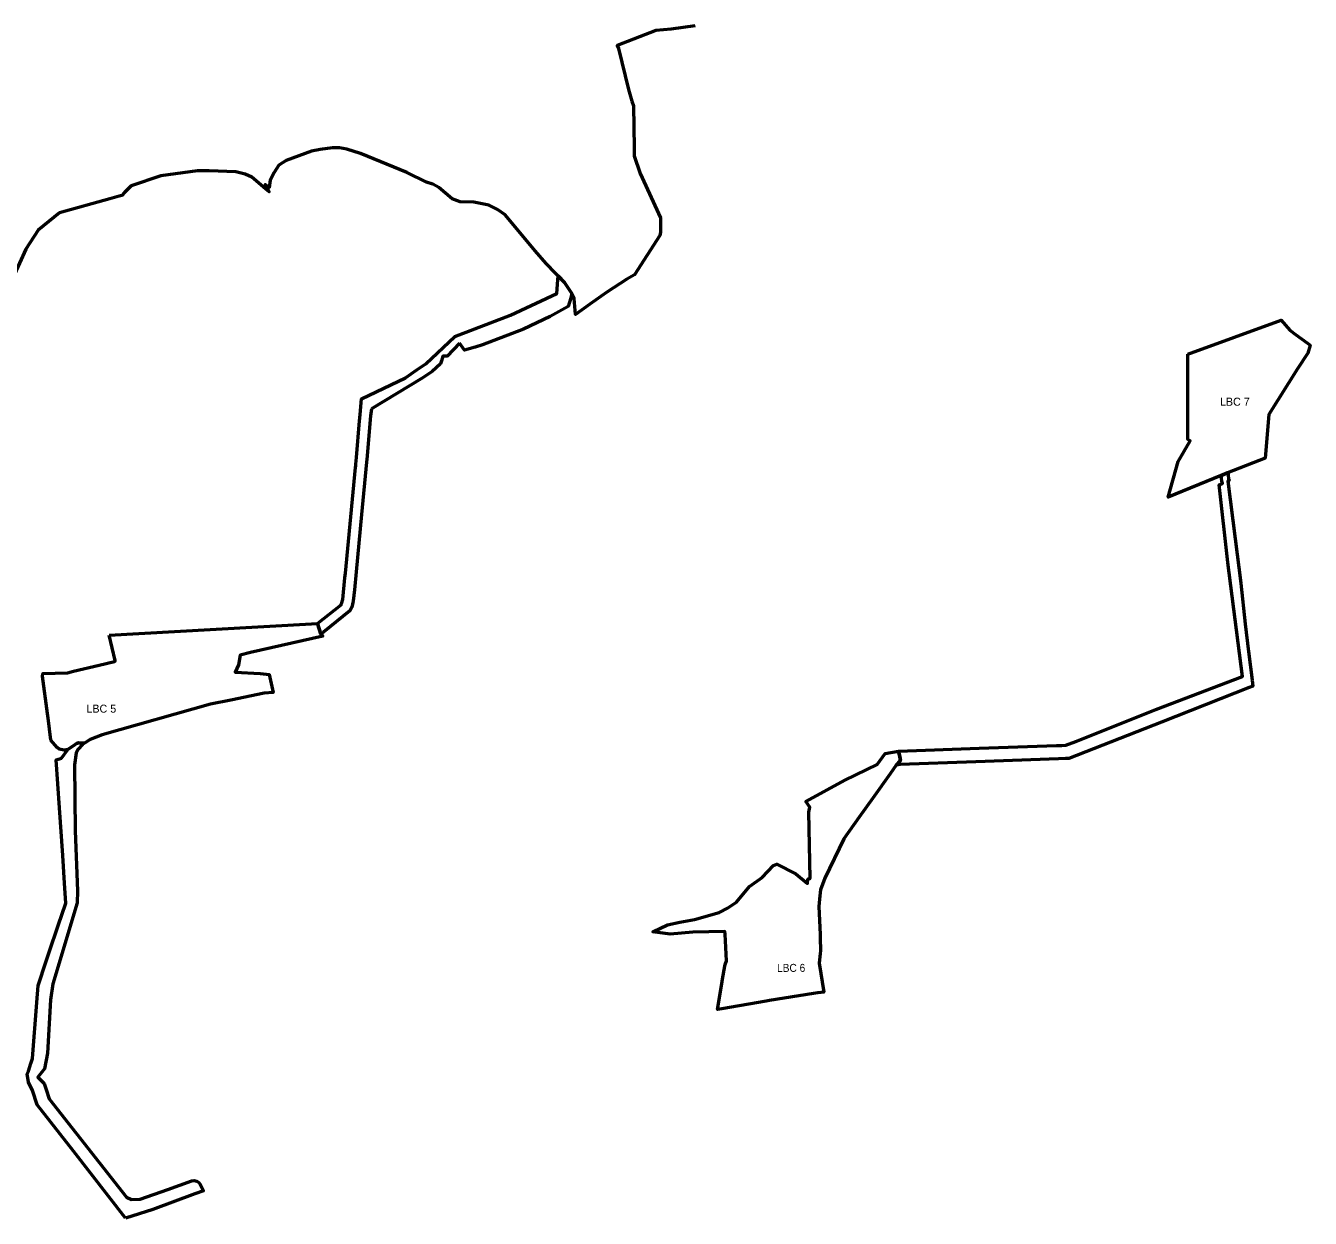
# Model space of a CAD drawing. Extents: x -650276 to -642570, y -1074314 to -1066553.
# Drawn here: x -644496 to -642570, y -1070907 to -1069118 of the extents above; entities that cross this region are included whole.
import ezdxf
from ezdxf.enums import TextEntityAlignment as Align

# ---------------------------------------------------------------- set-up
doc = ezdxf.new("R2010")
doc.units = 0
doc.header["$LTSCALE"] = 4.8
for name, color, linetype, lineweight in [('15', 7, 'Continuous', 53), ('23', 7, 'Continuous', 53), ('27', 7, 'Continuous', 53)]:
    doc.layers.add(name, color=color, linetype=linetype, lineweight=lineweight)
doc.layers.add('63', color=7, linetype='Continuous')

msp = doc.modelspace()

# ---------------------------------------------------------------- linework, layer by layer
at = {"layer": '15'}
for points in [[(-643492.12, -1069118.07), (-643528.05, -1069123.38), (-643550.79, -1069125.24), (-643609.08, -1069147.64), (-643607.02, -1069152.34), (-643592.11, -1069213.99), (-643586.8, -1069231.36), (-643584.68, -1069238.34), (-643583.55, -1069301.43), (-643583.34, -1069313.43), (-643574.54, -1069339.56), (-643543.95, -1069406.4), (-643544.06, -1069427.6), (-643545.07, -1069432.89), (-643582.77, -1069491.76), (-643594.49, -1069498.17), (-643624.65, -1069517.85), (-643649.94, -1069535.93), (-643671.53, -1069551.1), (-643673.34, -1069527.08), (-643676.9, -1069519.91), (-643688.19, -1069503.11), (-643715.22, -1069474.81), (-643731.98, -1069455.66), (-643776.78, -1069401.87), (-643788.63, -1069393.7), (-643801.36, -1069387.23), (-643823.72, -1069382.61), (-643844.28, -1069382.26), (-643856.58, -1069377.59), (-643876.34, -1069360.61), (-643885.22, -1069355.58), (-643894.84, -1069352.76), (-643924.42, -1069338.29), (-643993.91, -1069309.57), (-644014.19, -1069303.36), (-644025.24, -1069301.38), (-644035.89, -1069301.02), (-644054.35, -1069303.55), (-644067.08, -1069306.15), (-644105.5, -1069320.03), (-644116.33, -1069327.36), (-644123.21, -1069338.41), (-644129.09, -1069349.83), (-644130.85, -1069360.64), (-644136.88, -1069356.05), (-644130.55, -1069367.24), (-644136.29, -1069362.5), (-644157.02, -1069345.38), (-644166.58, -1069340.7), (-644180.96, -1069337.42), (-644220.78, -1069335.57), (-644238.42, -1069335.55), (-644293.29, -1069343.17), (-644337.6, -1069358.4), (-644347.56, -1069368.35), (-644351.83, -1069372.62), (-644355.7, -1069373.76)], [(-644355.7, -1069373.76), (-644369.87, -1069377.57), (-644445.36, -1069398.48), (-644477.24, -1069424.8), (-644495.46, -1069453.11), (-644514.85, -1069495)]]:
    msp.add_lwpolyline(points, dxfattribs=at)
at = {"layer": '23'}
for points in [[(-642753.18, -1069610.65), (-642613.34, -1069559.68), (-642600.39, -1069574.87), (-642592.12, -1069580.95), (-642574.11, -1069594.18), (-642569.7, -1069597.42), (-642573.53, -1069609.34), (-642588.93, -1069632.86), (-642631.9, -1069701.07), (-642637.44, -1069766.81), (-642693.99, -1069788.85), (-642703.57, -1069792.88), (-642782.69, -1069824.93), (-642767.89, -1069771.42), (-642750.08, -1069740.57), (-642753.25, -1069738.59)], [(-644370.87, -1070032.13), (-644219.33, -1070023.53), (-644058.55, -1070014.4), (-644053.18, -1070030.57), (-644050.12, -1070033.64), (-644159.02, -1070057.84), (-644174.12, -1070062.16), (-644177.01, -1070076.69), (-644181.81, -1070087.51), (-644144.13, -1070089.47), (-644130.91, -1070091.1), (-644125, -1070117.83), (-644138.24, -1070119.29), (-644188.44, -1070129.43), (-644218.65, -1070135.75), (-644381.21, -1070181.71), (-644399.15, -1070188.55), (-644407.55, -1070194.16), (-644416.67, -1070193.7), (-644419.51, -1070194.76), (-644421.88, -1070196.28), (-644432.53, -1070203.32), (-644438, -1070204.57), (-644445.9, -1070202.83), (-644448.76, -1070200.77), (-644458.1, -1070189.736), (-644462.35, -1070156.65), (-644463.28, -1070149.42), (-644470.55, -1070093.61), (-644470.17, -1070089.43), (-644433.19, -1070088.37), (-644423.99, -1070086.17), (-644385.73, -1070076.96), (-644362.55, -1070071.52), (-644361.571, -1070071.284), (-644361.74, -1070070.32)], [(-643306.64, -1070438.91), (-643304.73, -1070480.95), (-643304.63, -1070486.64), (-643304.23, -1070505.07), (-643304.71, -1070510.01), (-643306.03, -1070524.13), (-643299.3, -1070567.28), (-643307.99, -1070568.66), (-643314.51, -1070569.69), (-643380.35, -1070580.14), (-643385.72, -1070580.86), (-643452.22, -1070592.35), (-643458.42, -1070593.43), (-643452.14, -1070554.77), (-643450.98, -1070547.74), (-643447.79, -1070528.63), (-643446.89, -1070526.01), (-643445.1, -1070520.47), (-643447.14, -1070480.35), (-643447.34, -1070476.49), (-643495.67, -1070477.55), (-643529.45, -1070480.45), (-643555.57, -1070477.1), (-643533.33, -1070466.42), (-643514.92, -1070462.62), (-643492.91, -1070458.54), (-643456.25, -1070448), (-643443.57, -1070441.55), (-643429.94, -1070432.58), (-643410.62, -1070409.09), (-643391.45, -1070395.38), (-643374.72, -1070377.63), (-643369.66, -1070375.29), (-643341.3, -1070390.01), (-643323.48, -1070404.29), (-643323.32, -1070398.24), (-643319.68, -1070396.52), (-643321.63, -1070297.65), (-643320, -1070290.2), (-643326.26, -1070281.43), (-643267.55, -1070249.49), (-643219.4, -1070225.8), (-643207.1, -1070209.72), (-643187.06, -1070205.98), (-643185.16, -1070214.62), (-643184.22, -1070220.08), (-643190.42, -1070226.99), (-643199.67, -1070240.13), (-643225.66, -1070276.41), (-643246.36, -1070305.06), (-643269.16, -1070337.59), (-643297.63, -1070396.36), (-643303.88, -1070414.2), (-643305.45, -1070427.92)]]:
    msp.add_lwpolyline(points, close=True, dxfattribs=at)
at = {"layer": '27'}
for points in [[(-643852.51, -1069584.08), (-643769.08, -1069551.96), (-643699.23, -1069519.48), (-643697.85, -1069499.21), (-643697.686, -1069493.168), (-643688.19, -1069503.11), (-643676.9, -1069519.91), (-643678.24, -1069526.44), (-643682.27, -1069539.41), (-643709.33, -1069554.14), (-643749.64, -1069573.35), (-643811.16, -1069596.45), (-643822.06, -1069600.07), (-643837.72, -1069604.62), (-643845.304, -1069594.087)], [(-643994.36, -1069701.05), (-643992.34, -1069677.76), (-643926.229, -1069646.367), (-643909.616, -1069634.267), (-643895.951, -1069625.069), (-643852.51, -1069584.08)], [(-643845.304, -1069594.087), (-643863.92, -1069613.9), (-643870.44, -1069613.56), (-643872.55, -1069620.75), (-643873.82, -1069625.05), (-643886.62, -1069636.87), (-643901.55, -1069646.92), (-643977.582, -1069692.76)], [(-643977.582, -1069692.76), (-643978.85, -1069703.4), (-643984.44, -1069768.58), (-643984.845, -1069772.863), (-643992.27, -1069851.31), (-644000.52, -1069937.19), (-644003.06, -1069964.06), (-644005.06, -1069981.28), (-644006.96, -1069990.34), (-644009.95, -1069995.74), (-644049.311, -1070027.453), (-644051.913, -1070029.549), (-644053.18, -1070030.57), (-644058.55, -1070014.4), (-644022.99, -1069986.58), (-644022.43, -1069984.87), (-644020.26, -1069978.38), (-644017.15, -1069945.93), (-644016.47, -1069938.99), (-644001.29, -1069780.7), (-644001.04, -1069778.063), (-644000.79, -1069775.42), (-643999.94, -1069765.62), (-643995.17, -1069710.42), (-643994.36, -1069701.05)], [(-644485.61, -1070714.95), (-644491.42, -1070702.64), (-644493.5, -1070689.75), (-644491.82, -1070685.92), (-644488.01, -1070674.2), (-644485.64, -1070666.7), (-644479.06, -1070583.13), (-644476.94, -1070557.45), (-644464.98, -1070521.13), (-644460.5, -1070507.68), (-644447.14, -1070467.28), (-644435.51, -1070433.85), (-644437.53, -1070404.1), (-644440.36, -1070362.62), (-644445.28, -1070290.84), (-644450.15, -1070219.06), (-644442.2, -1070216.72), (-644432.53, -1070203.32), (-644421.88, -1070196.28), (-644419.51, -1070194.76), (-644416.67, -1070193.7), (-644407.55, -1070194.16), (-644410.56, -1070196.2), (-644417.36, -1070203.24), (-644420.14, -1070208.56), (-644422.5, -1070226.42), (-644421.45, -1070325.29), (-644418.23, -1070415.62), (-644418.69, -1070433.36), (-644455.2, -1070554.88), (-644458.85, -1070579.04), (-644463.28, -1070659.06), (-644467.84, -1070682.37), (-644477.46, -1070695.09), (-644468.1, -1070704.23)], [(-644468.1, -1070704.23), (-644465.31, -1070713.25), (-644460.82, -1070727.21), (-644344.86, -1070875.09), (-644337.15, -1070878.64), (-644324.34, -1070877.71), (-644282.77, -1070863.19), (-644246.93, -1070850.52), (-644243.15, -1070849.89), (-644239.47, -1070850.71), (-644236.3, -1070852.87), (-644234.66, -1070855.08), (-644229.12, -1070865.52), (-644242.29, -1070869.82), (-644305.07, -1070893.39), (-644346.21, -1070906.61)], [(-644346.21, -1070906.61), (-644424.37, -1070806.03), (-644478.67, -1070736.28), (-644485.61, -1070714.95)]]:
    msp.add_lwpolyline(points, dxfattribs=at)
msp.add_lwpolyline([(-643066.26, -1070201.69), (-642950.42, -1070197.58), (-642942.12, -1070197.4), (-642936.02, -1070197.23), (-642921.03, -1070191.32), (-642801.19, -1070143.75), (-642671.23, -1070094.16), (-642693.2, -1069922.89), (-642706.3, -1069806.69), (-642701.17, -1069804.49), (-642701.95, -1069802.35), (-642702.12, -1069801.89), (-642702.69, -1069795.44), (-642702.88, -1069794.95), (-642703.57, -1069792.88), (-642693.99, -1069788.85), (-642693, -1069791.05), (-642692.81, -1069791.58), (-642692.18, -1069798.08), (-642691.98, -1069798.57), (-642691.36, -1069800.03), (-642693.36, -1069800.94), (-642682.32, -1069887.43), (-642674.06, -1069953.91), (-642667.14, -1070015.01), (-642662.41, -1070056.78), (-642657.01, -1070099.49), (-642655.863, -1070108.525), (-642661.13, -1070110.48), (-642792.87, -1070162.36), (-642931.88, -1070217.1), (-642936.88, -1070217.27), (-642947.42, -1070217.64), (-643071.16, -1070221.95), (-643184.86, -1070225.91), (-643190.42, -1070226.99), (-643184.22, -1070220.08), (-643185.16, -1070214.62), (-643187.06, -1070205.98)], close=True, dxfattribs=at)

# ---------------------------------------------------------------- texts
at = {"layer": '63'}
for s, p in [('LBC 7', (-642682.822, -1069687.985)), ('LBC 5', (-644382.463, -1070148.313))]:
    msp.add_text(s, height=12, dxfattribs=at).set_placement(p, align=Align.CENTER)
at = {"layer": '63', "width": 0.95}
msp.add_text('LBC 6', height=12, dxfattribs=at).set_placement((-643348.135, -1070537.056), align=Align.CENTER)

doc.saveas('drawing.dxf')
